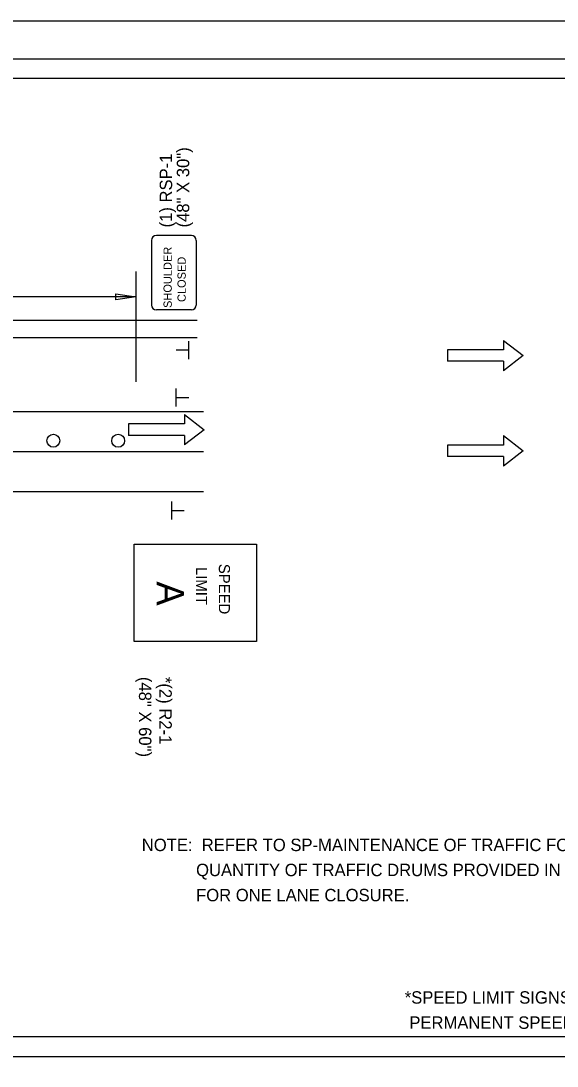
# Model space of a CAD drawing. Extents: x 1373222 to 1374279, y 380783 to 380996.
# Drawn here: x 1374149.3 to 1374204.6, y 380888.9 to 380996.5 of the extents above; entities that cross this region are included whole.
import ezdxf

# ---------------------------------------------------------------- set-up
doc = ezdxf.new("R2010")
doc.units = 0
for name, color, linetype in [('R_Border', 7, 'Continuous'), ('R_Border Plan-Plan', 7, 'Continuous'), ('R_Draft', 7, 'Continuous'), ('R_No Plot', 7, 'Continuous')]:
    doc.layers.add(name, color=color, linetype=linetype)

msp = doc.modelspace()

# ---------------------------------------------------------------- linework, layer by layer
at = {"layer": 'R_Border'}
msp.add_line((1373957.81, 380992.59), (1374273.99, 380992.59), dxfattribs=at)
at = {"layer": 'R_Border Plan-Plan'}
msp.add_line((1373957.81, 380889.86), (1374273.99, 380889.86), dxfattribs=at)
at = {"layer": 'R_Draft'}
for p, q in [((1374166.91, 380974.39), (1374163.3, 380974.39)), ((1374162.8, 380973.89), (1374162.8, 380967.23)), ((1374167.41, 380973.89), (1374167.41, 380967.23)), ((1374161.19, 380970.69), (1374161.19, 380959.32)), ((1374161.19, 380968.06), (1374099.37, 380968.06)), ((1374159.13, 380967.75), (1374159.13, 380968.37)), ((1374159.13, 380968.37), (1374161.19, 380968.06)), ((1374161.19, 380968.06), (1374159.13, 380967.75)), ((1374166.91, 380966.72), (1374163.3, 380966.72)), ((1374061.27, 380965.67), (1374167.51, 380965.67)), ((1374061.49, 380963.9), (1374167.5, 380963.9)), ((1374166.65, 380961.66), (1374166.65, 380963.51)), ((1374199.06, 380963.59), (1374199.06, 380962.61)), ((1374199.06, 380963.59), (1374201.09, 380962.02)), ((1374166.62, 380962.58), (1374165.36, 380962.58)), ((1374199.06, 380962.61), (1374193.31, 380962.61)), ((1374193.31, 380962.61), (1374193.31, 380961.44)), ((1374199.06, 380961.44), (1374193.31, 380961.44)), ((1374201.09, 380962.02), (1374199.06, 380960.46)), ((1374199.06, 380961.44), (1374199.06, 380960.46)), ((1374165.36, 380956.79), (1374165.36, 380958.65)), ((1374165.39, 380957.71), (1374166.66, 380957.71)), ((1374132.4, 380956.27), (1374168.15, 380956.27)), ((1374166.19, 380955.95), (1374166.19, 380954.98)), ((1374166.19, 380955.95), (1374168.23, 380954.39)), ((1374166.19, 380954.98), (1374160.44, 380954.98)), ((1374160.44, 380954.98), (1374160.44, 380953.8)), ((1374166.19, 380953.8), (1374160.44, 380953.8)), ((1374168.23, 380954.39), (1374166.19, 380952.83)), ((1374166.19, 380953.8), (1374166.19, 380952.83)), ((1374199.06, 380953.78), (1374199.06, 380952.8)), ((1374199.06, 380953.78), (1374201.09, 380952.21)), ((1374199.06, 380952.8), (1374193.31, 380952.8)), ((1374193.31, 380952.8), (1374193.31, 380951.63)), ((1374132.92, 380952.15), (1374168.15, 380952.15)), ((1374199.06, 380951.63), (1374193.31, 380951.63)), ((1374201.09, 380952.21), (1374199.06, 380950.65)), ((1374199.06, 380951.63), (1374199.06, 380950.65)), ((1374133.7, 380948.03), (1374168.15, 380948.03)), ((1374164.88, 380945.14), (1374164.88, 380946.99)), ((1374164.91, 380946.06), (1374166.18, 380946.06))]:
    msp.add_line(p, q, dxfattribs=at)
msp.add_lwpolyline([(1374173.63, 380932.6), (1374161.02, 380932.6), (1374161.02, 380942.6), (1374173.63, 380942.6)], close=True, dxfattribs=at)
for centre in [(1374152.69, 380953.26), (1374159.37, 380953.26)]:
    msp.add_circle(centre, 0.667, dxfattribs=at)
for centre, start, end in [((1374163.3, 380973.89), 90, 180), ((1374166.91, 380973.89), 360, 90), ((1374163.3, 380967.23), 180, 270), ((1374166.91, 380967.23), 270, 360)]:
    msp.add_arc(centre, 0.505, start, end, dxfattribs=at)
at = {"layer": 'R_No Plot'}
for points in [[(1373945.41, 380996.49), (1374278.75, 380996.49), (1374278.75, 380783.15), (1373945.41, 380783.15)], [(1374271.99, 380891.86), (1373959.81, 380891.86), (1373959.81, 380990.59), (1374209.35, 380990.59), (1374209.35, 380980.71), (1374226.89, 380980.71), (1374250.99, 380980.71), (1374250.99, 380958.38), (1374271.99, 380958.38)], [(1373959.81, 380990.59), (1374209.35, 380990.59), (1374209.35, 380980.71), (1374226.89, 380980.71), (1374250.99, 380980.71), (1374250.99, 380958.38), (1374271.99, 380958.38), (1374271.99, 380789.13), (1373959.81, 380789.13)]]:
    msp.add_lwpolyline(points, close=True, dxfattribs=at)

# ---------------------------------------------------------------- texts
at = {"layer": 'R_Draft'}
for s, height, rotation, p in [('(1) RSP-1', 1.28, 90, (1374164.93, 380975.22)), ('(48" X 30")', 1.28, 90, (1374166.69, 380975.22)), ('SHOULDER', 0.848, 90, (1374164.89, 380966.93)), ('CLOSED', 0.848, 90, (1374166.33, 380967.54)), ('LIMIT', 1.146, 270, (1374167.39, 380940.26)), ('SPEED', 1.146, 270, (1374169.74, 380940.58)), ('A', 2.79, 270, (1374163.35, 380938.77)), ('*(2) R2-1', 1.28, 270, (1374163.61, 380928.94)), ('(48" X 60")', 1.28, 270, (1374161.51, 380928.94)), ('*SPEED LIMIT SIGNS SHALL MATCH', 1.28, 360, (1374188.89, 380895.29)), (' PERMANENT SPEED LIMIT.', 1.28, 360, (1374188.89, 380892.7))]:
    msp.add_text(s, height=height, rotation=rotation, dxfattribs=at).set_placement(p)
for s, p in [('NOTE:  REFER TO SP-MAINTENANCE OF TRAFFIC FOR LANE CLOSURE LIMITATIONS AND RESTRICTIONS.  ', (1374161.8, 380911)), (' QUANTITY OF TRAFFIC DRUMS PROVIDED IN THE CONTRACT IS THE MAXIMUM NUMBER REQUIRED', (1374166.92, 380908.42)), (' FOR ONE LANE CLOSURE.', (1374166.92, 380905.83))]:
    msp.add_text(s, height=1.28, dxfattribs=at).set_placement(p)

doc.saveas('drawing.dxf')
